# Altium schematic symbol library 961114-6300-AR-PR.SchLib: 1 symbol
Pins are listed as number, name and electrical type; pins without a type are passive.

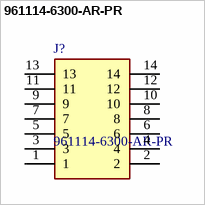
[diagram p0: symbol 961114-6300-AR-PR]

## 961114-6300-AR-PR
designator J?
Headers & Wire Housings 14P STR SMT SR GOLD 5.3MM MATING PIN; Manufacturer_Name: 3M; Geometry.Height: 9.6mm
footprint 9611146300ARPR
pins: 1, 2, 3, 4, 5, 6, 7, 8, 9, 10, 11, 12, 13, 14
